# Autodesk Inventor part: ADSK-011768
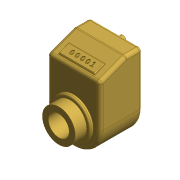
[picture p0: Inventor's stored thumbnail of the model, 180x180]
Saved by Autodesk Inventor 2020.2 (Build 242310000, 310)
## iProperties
Created: 1999-11
Part Number: ADSK-011768
Description: COUNTER,SHAFT,DIGITAL READOUT,CW,0.750B
Document SubType Name: Modeling
Designer: mpflueger
Material: Générique
Density: 1 g/cm^3
Appearance: Vorgabe
Mass: 122.088 g
Surface Area: 210.868 cm^2
Volume: 122.088 cm^3
Control State: 0
Master: False
Checked Out: False
Shininess: 0.0
Length Units: 11269
Angle Units: 11279
Time Units: 11290
Mass Units: 11283
Length Display Precision: 3
Angle Display Precision: 2
Compacted: True
Dimensions: 80x66,7x50,8 mm
Mass: 0,122 kg
VLT_Material: Generic
Density: 0.0
Volumn: 0.0
Area: 0.0
PropertySet Name: Model Information
Author: mpflueger
Revision Number: -
Title: COUNTER,SHAFT,DIGITAL READOUT,CW,0.750B
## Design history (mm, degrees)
node "Solide1"
  node "Extrusion1" dims "d2" = 41.275, "d3" = 0
  node "Extrusion2" dims "d5" = 3.175, "d6" = 0
  node "Extrusion3" dims "d8" = 11.0998, "d9" = 0
  node "Extrusion4" dims "d12" = 6.35, "d13" = 0
  node "Extrusion5" dims "d14" = 1.5875, "d15" = -45 deg
  node "Extrusion6" dims "d17" = 14.2875, "d18" = 0
  node "Extrusion7" dims "d20" = 14.2875, "d21" = 0
  node "Chamfer1" dims "d22" = 25.4, "d23" = 9.525, "d50" = 45 deg
  node "Extrusion8" dims "d28" = 1.5875, "d29" = 0
  node "Chamfer2" dims "d30" = 0.79375, "d31" = 0.79375, "d51" = 45 deg
  node "Fillet1" dims "d32" = 3.175, "d33" = 3.175, "d34" = 1.5875
  node "Extrusion9" dims "d35" = 1.5875, "d36" = 15 deg
workplane "Arbeitsebene1"
sketch "Sketch4"
  geometry: C1 r 3 at (-25.4, 67.4); A1 r 25.4 centre (-25.4, 25.4) between (-50.8, 25.4) and (0, 25.4) reference
  constraints: 1 centre point
  dimensions: "d10" = 42 distance of C1.centre A1.centre; "d11" = 6 diameter of C1
sketch "Sketch7"
  geometry: C1 r 20.638 at (0, 0) reference; C2 r 10 at (0, 0)
  constraints: 1 centre point, 1 coincident
  dimensions: "d19" = 20 diameter of C2
node "Corps solides"
node "Corps surfaciques"
sketch "Sketch1"
  geometry: L1 (50.8, 25.4)-(50.8, 76.2); L2 (50.8, 76.2)-(0, 76.2); L3 (0, 76.2)-(0, 25.4); A1 r 25.4 centre (25.4, 25.4) between (0, 25.4) and (50.8, 25.4)
  constraints: 6 end point, 2 point on circle, 2 tangent, 1 centre point, 1 parallel
  dimensions: "d0" = 50.8 distance from line of A1.centre L2; "d1" = 50.8 distance of L1.end L2.end
sketch "Sketch2"
  geometry: C1 r 19.05 at (25.4, 25.4); A1 r 25.4 centre (25.4, 25.4) between (0, 25.4) and (50.8, 25.4) reference
  constraints: 1 centre point, 1 coincident
  dimensions: "d4" = 38.1 diameter of C1
sketch "Sketch3"
  geometry: C1 r 19.05 at (0, 0) reference; C2 r 15.875 at (0, 0)
  constraints: 1 centre point, 1 coincident
  dimensions: "d7" = 31.75 diameter of C2
sketch "Sketch5"
  geometry: C1 r 3 at (0, 0) reference; C2 r 1.587 at (0, 0)
  constraints: 1 centre point, 1 coincident
sketch "Sketch6"
  geometry: C1 r 20.638 at (-25.4, 25.4); A1 r 25.4 centre (-25.4, 25.4) between (-50.8, 25.4) and (0, 25.4) reference
  constraints: 1 centre point, 1 coincident
  dimensions: "d16" = 41.275 diameter of C1
sketch "Sketch8"
  geometry: L1 (7.938, -23.952)-(42.862, -23.952); L2 (42.862, -23.952)-(42.862, -12.84); L3 (42.862, -12.84)-(7.937, -12.84); L4 (7.937, -12.84)-(7.938, -23.952)
  constraints: 8 end point, 2 parallel, 1 horizontal, 1 perpendicular
  dimensions: "d24" = 11.1125 distance of L3.end L1.start; "d25" = 34.925 distance of L1.start L1.end
sketch "Sketch9"
  geometry: L1 (8.731, -23.158)-(8.731, -13.633) reference; L2 (34.96, -20.529)-(38.224, -20.529); L3 (38.224, -20.529)-(38.224, -19.767); L4 (38.224, -19.767)-(37.015, -19.767); L5 (37.015, -19.767)-(37.015, -15.953); L6 (37.015, -15.953)-(36.106, -15.953); L7 (36.106, -15.953)-(35.178, -16.721); L8 (35.178, -16.721)-(35.604, -17.236); L9 (35.604, -17.236)-(36.253, -16.699); L10 (36.253, -16.699)-(36.253, -19.767); L11 (36.253, -19.767)-(34.96, -19.767); L12 (34.96, -19.767)-(34.96, -20.529); 8 further points; 8 other entities
  constraints: 22 end point, 6 parallel, 4 coincident, 4 perpendicular, 16 other
  dimensions: "d38" = 7.62 distance from line of point (16.351, -18.291) L1; "d44" = 0.762 distance of L2.end L3.end; "d45" = 0.762 distance of L11.end L2.start (= d44); "d46" = 0.762 distance between parallel lines of L5 L10 (= d45); "d47" = 5.08 distance of point (21.431, -18.291) point (16.351, -18.291); "d48" = 5.08 distance of point (26.511, -18.291) point (21.431, -18.291); "d49" = 5.08 distance of point (31.591, -18.291) point (26.511, -18.291)
